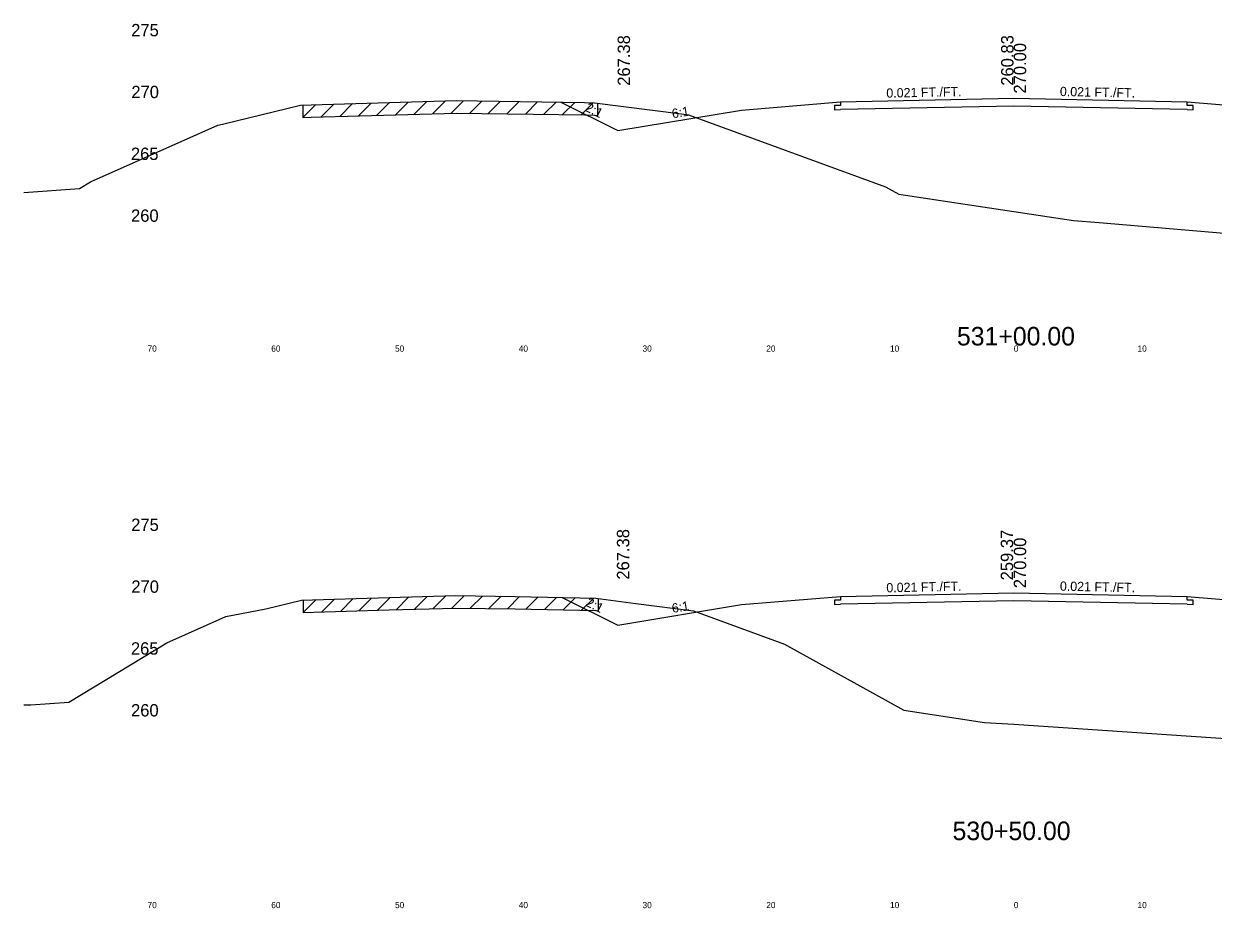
# Model space of a CAD drawing. Extents: x 1000 to 1162, y 999 to 8520.
# Drawn here: x 1000 to 1096.1, y 5024.5 to 5096 of the extents above; entities that cross this region are included whole.
import ezdxf

# ---------------------------------------------------------------- set-up
doc = ezdxf.new("R2010")
doc.units = 0
for name, color, linetype in [('Level 10', 7, 'Continuous'), ('Level 11', 7, 'Continuous'), ('Level 12', 7, 'Continuous'), ('Level 3', 7, 'Continuous'), ('Level 32', 7, 'Continuous'), ('Level 33', 7, 'Continuous'), ('Level 56', 7, 'Continuous'), ('Level 59', 7, 'Continuous'), ('Level 6', 7, 'Continuous'), ('Level 60', 7, 'Continuous'), ('Level 61', 7, 'Continuous'), ('Level 7', 7, 'Continuous')]:
    doc.layers.add(name, color=color, linetype=linetype)

msp = doc.modelspace()

# ---------------------------------------------------------------- linework, layer by layer
at = {"layer": 'Level 11'}
for p, q in [((1066, 5089.409), (1065.5, 5089.398)), ((1065.5, 5089.398), (1065.5, 5089.058)), ((1066, 5089.709), (1066, 5089.409)), ((1094, 5089.409), (1094, 5089.709)), ((1094.5, 5089.398), (1094, 5089.409)), ((1094.5, 5089.058), (1094.5, 5089.398)), ((1065.5, 5089.058), (1066, 5089.069)), ((1094, 5089.069), (1094.5, 5089.058)), ((1066, 5049.409), (1065.5, 5049.398)), ((1065.5, 5049.398), (1065.5, 5049.058)), ((1065.5, 5049.058), (1066, 5049.069)), ((1066, 5049.709), (1066, 5049.409)), ((1094, 5049.409), (1094, 5049.709)), ((1094.5, 5049.398), (1094, 5049.409)), ((1094, 5049.069), (1094.5, 5049.058)), ((1094.5, 5049.058), (1094.5, 5049.398))]:
    msp.add_line(p, q, dxfattribs=at)
at = {"layer": 'Level 12'}
for p, q in [((1080, 5089.36), (1066, 5089.069)), ((1094, 5089.069), (1080, 5089.36)), ((1080, 5049.36), (1066, 5049.069)), ((1094, 5049.069), (1080, 5049.36))]:
    msp.add_line(p, q, dxfattribs=at)
at = {"layer": 'Level 59'}
for p, q in [((1066, 5089.709), (1080, 5090)), ((1080, 5090), (1094, 5089.709)), ((1066, 5049.709), (1080, 5050)), ((1080, 5050), (1094, 5049.709))]:
    msp.add_line(p, q, dxfattribs=at)
at = {"layer": 'Level 6'}
for p, q in [((1058, 5089.042), (1066, 5089.709)), ((1094, 5089.709), (1102, 5089.042)), ((1058, 5049.042), (1066, 5049.709)), ((1094, 5049.709), (1102, 5049.042))]:
    msp.add_line(p, q, dxfattribs=at)
at = {"layer": 'Level 60'}
for p, q in [((1016.071, 5087.896), (1022.363, 5089.436)), ((1022.363, 5089.436), (1023.22, 5089.462)), ((1023.22, 5089.462), (1034.946, 5089.797)), ((1034.946, 5089.797), (1045.302, 5089.648)), ((1045.302, 5089.648), (1046.118, 5089.631)), ((1046.118, 5089.631), (1053.154, 5088.719)), ((1053.154, 5088.719), (1053.717, 5088.644)), ((1053.717, 5088.644), (1069.626, 5082.838)), ((1005.38, 5083.228), (1015.692, 5087.825)), ((1015.692, 5087.825), (1016.071, 5087.896)), ((1000, 5082.383), (1004.51, 5082.699)), ((1004.51, 5082.699), (1005.38, 5083.228)), ((1069.626, 5082.838), (1070.702, 5082.243)), ((1070.702, 5082.243), (1080, 5080.827)), ((1080, 5080.827), (1084.816, 5080.094)), ((1084.816, 5080.094), (1086.91, 5079.955)), ((1086.91, 5079.955), (1116.186, 5077.421)), ((1019.552, 5048.696), (1022.452, 5049.406)), ((1022.452, 5049.406), (1029.513, 5049.617)), ((1029.513, 5049.617), (1034.922, 5049.771)), ((1034.922, 5049.771), (1039.698, 5049.703)), ((1039.698, 5049.703), (1046.215, 5049.566)), ((1046.215, 5049.566), (1049.468, 5049.144)), ((1049.468, 5049.144), (1054.114, 5048.529)), ((1011.548, 5045.96), (1016.317, 5048.086)), ((1016.317, 5048.086), (1019.552, 5048.696)), ((1054.114, 5048.529), (1061.472, 5045.844)), ((1003.634, 5041.157), (1011.548, 5045.96)), ((1061.472, 5045.844), (1071.106, 5040.518)), ((1000, 5040.942), (1000.569, 5040.941)), ((1000.569, 5040.941), (1003.634, 5041.157)), ((1071.106, 5040.518), (1077.643, 5039.523)), ((1077.643, 5039.523), (1080, 5039.366)), ((1080, 5039.366), (1097.911, 5038.174))]:
    msp.add_line(p, q, dxfattribs=at)
at = {"layer": 'Level 61'}
for p, q in [((1023.567, 5089.472), (1022.537, 5088.441)), ((1022.537, 5089.441), (1022.537, 5088.441)), ((1025.066, 5089.514), (1024.037, 5088.485)), ((1026.566, 5089.557), (1025.537, 5088.528)), ((1028.066, 5089.6), (1027.037, 5088.571)), ((1029.566, 5089.643), (1028.537, 5088.613)), ((1031.066, 5089.686), (1030.037, 5088.656)), ((1032.566, 5089.729), (1031.537, 5088.699)), ((1034.066, 5089.771), (1033.037, 5088.742)), ((1035.54, 5089.788), (1034.537, 5088.785)), ((1037.023, 5089.767), (1036.037, 5088.781)), ((1038.523, 5089.745), (1037.537, 5088.759)), ((1040.023, 5089.724), (1039.037, 5088.738)), ((1041.523, 5089.702), (1040.537, 5088.716)), ((1043.023, 5089.681), (1042.037, 5088.695)), ((1044.523, 5089.659), (1043.537, 5088.673)), ((1046.018, 5089.633), (1045.037, 5088.652)), ((1046.387, 5088.596), (1046.387, 5089.596)), ((1022.537, 5088.441), (1023.22, 5088.462)), ((1023.22, 5088.462), (1034.946, 5088.797)), ((1034.946, 5088.797), (1045.302, 5088.648)), ((1045.302, 5088.648), (1046.118, 5088.631)), ((1046.118, 5088.631), (1046.387, 5088.596)), ((1023.61, 5049.44), (1022.58, 5048.41)), ((1022.58, 5049.41), (1022.58, 5048.41)), ((1025.11, 5049.485), (1024.08, 5048.454)), ((1026.61, 5049.53), (1025.58, 5048.499)), ((1028.11, 5049.575), (1027.08, 5048.544)), ((1029.61, 5049.62), (1028.58, 5048.589)), ((1031.109, 5049.663), (1030.08, 5048.633)), ((1032.609, 5049.705), (1031.58, 5048.676)), ((1034.109, 5049.748), (1033.08, 5048.719)), ((1035.58, 5049.762), (1034.58, 5048.762)), ((1037.065, 5049.741), (1036.08, 5048.755)), ((1038.565, 5049.719), (1037.58, 5048.733)), ((1040.063, 5049.695), (1039.08, 5048.712)), ((1041.559, 5049.664), (1040.58, 5048.684)), ((1043.059, 5049.632), (1042.08, 5048.653)), ((1044.559, 5049.601), (1043.58, 5048.621)), ((1046.059, 5049.569), (1045.08, 5048.59)), ((1046.43, 5048.538), (1046.43, 5049.538)), ((1022.58, 5048.41), (1029.513, 5048.617)), ((1029.513, 5048.617), (1034.922, 5048.771)), ((1034.922, 5048.771), (1039.698, 5048.703)), ((1039.698, 5048.703), (1046.215, 5048.566)), ((1046.215, 5048.566), (1046.43, 5048.538))]:
    msp.add_line(p, q, dxfattribs=at)
at = {"layer": 'Level 7'}
for p, q in [((1043.401, 5089.675), (1048, 5087.376)), ((1048, 5087.376), (1058, 5089.042)), ((1043.505, 5049.623), (1048, 5047.376)), ((1048, 5047.376), (1058, 5049.042))]:
    msp.add_line(p, q, dxfattribs=at)

# ---------------------------------------------------------------- texts
at = {"layer": 'Level 10'}
for s, p in [('260.83', (1079.977, 5091.005)), ('259.37', (1079.947, 5051.005))]:
    msp.add_text(s, height=1, rotation=90, dxfattribs=at).set_placement(p)
at = {"layer": 'Level 11'}
for s, p in [(' 275', (1008.307, 5095)), (' 270', (1008.319, 5090)), (' 265', (1008.284, 5085)), (' 260', (1008.295, 5080)), (' 275', (1008.307, 5055)), (' 270', (1008.319, 5050)), (' 265', (1008.284, 5045)), (' 260', (1008.295, 5040))]:
    msp.add_text(s, height=1, dxfattribs=at).set_placement(p)
at = {"layer": 'Level 3'}
for s, p in [('531+00.00', (1075.406, 5070)), ('530+50.00', (1075.051, 5030))]:
    msp.add_text(s, height=1.5, dxfattribs=at).set_placement(p)
at = {"layer": 'Level 32'}
for s, rotation, p in [('0.021 FT./FT.', 1.19158, (1069.709, 5090.036)), ('0.021 FT./FT.', 358.80842, (1083.72, 5090.173)), ('2:1', 333.43495, (1045.305, 5089.003)), ('6:1', 9.46232, (1052.435, 5088.368)), ('0.021 FT./FT.', 1.19158, (1069.709, 5050.036)), ('0.021 FT./FT.', 358.80842, (1083.72, 5050.173)), ('2:1', 333.43495, (1045.357, 5048.976)), ('6:1', 9.46232, (1052.435, 5048.368))]:
    msp.add_text(s, height=0.75, rotation=rotation, dxfattribs=at).set_placement(p)
at = {"layer": 'Level 33'}
for p in [(1048.988, 5091.003), (1048.927, 5051.064)]:
    msp.add_text('267.38', height=1, rotation=90, dxfattribs=at).set_placement(p)
at = {"layer": 'Level 56'}
for s, p in [('70', (1010, 5069.5)), ('60', (1020, 5069.5)), ('50', (1030, 5069.5)), ('40', (1040, 5069.5)), ('30', (1050, 5069.5)), ('20', (1060, 5069.5)), ('10', (1070, 5069.5)), ('0', (1080, 5069.5)), ('10', (1090, 5069.5)), ('70', (1010, 5024.5)), ('60', (1020, 5024.5)), ('50', (1030, 5024.5)), ('40', (1040, 5024.5)), ('30', (1050, 5024.5)), ('20', (1060, 5024.5)), ('10', (1070, 5024.5)), ('0', (1080, 5024.5)), ('10', (1090, 5024.5))]:
    msp.add_text(s, height=0.5, dxfattribs=at).set_placement(p)
at = {"layer": 'Level 59'}
for p in [(1081, 5090), (1081, 5050)]:
    msp.add_text(' 270.00', height=1, rotation=90, dxfattribs=at).set_placement(p)

doc.saveas('drawing.dxf')
